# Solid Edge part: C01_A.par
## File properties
Author: edge
Template: Normal.par
Last saved by: edge
Revision: 16
Application: Solid Edge
面のスタイル: Gray
Coef. of Thermal Exp: 0.0
Thermal Conductivity: 0.0
Specific Heat: 0.0
Modulus of Elasticity: 0.0
Poission's Ratio: 0.0
Yield Stress: 0.0
Ultimate Stress: 0.0
Elongation: 0.0
文書内容のタイプ: 0
Accuracy: 0.990
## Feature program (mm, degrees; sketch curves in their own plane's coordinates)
sketch for "unnamed Protrusion 1" plane through (0, 0, 0) normal (0, -1, 0) x-axis (1, 0, 0)
  line (-40, 40) -> (-40, -40)
  line (-40, -40) -> (40, -40)
  line (40, -40) -> (40, 0)
  line (40, 0) -> (0, 0)
  line (0, 0) -> (0, 40)
  line (0, 40) -> (-40, 40)
  dimension (linear) = 40
  dimension (linear) = 40
extrude "unnamed Protrusion 1" add finite 80 symmetric
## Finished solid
Body 1: solid body, 8 faces, 18 edges, 12 vertices.
  Faces by surface: plane 8
  Edges by curve: line 18
Bounding box of the edges (mm): 80.000 x 80.000 x 80.000, from (-40, -40, -40) to (40, 40, 40).
Planar faces by outward normal: +x 2, +y 1, +z 2, -x 1, -y 1, -z 1
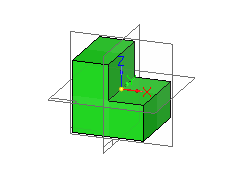
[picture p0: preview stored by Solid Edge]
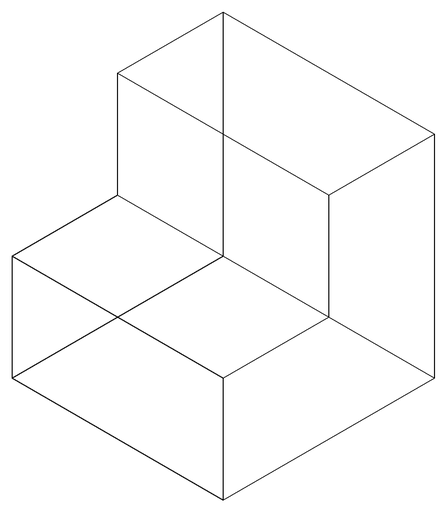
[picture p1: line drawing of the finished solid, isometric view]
